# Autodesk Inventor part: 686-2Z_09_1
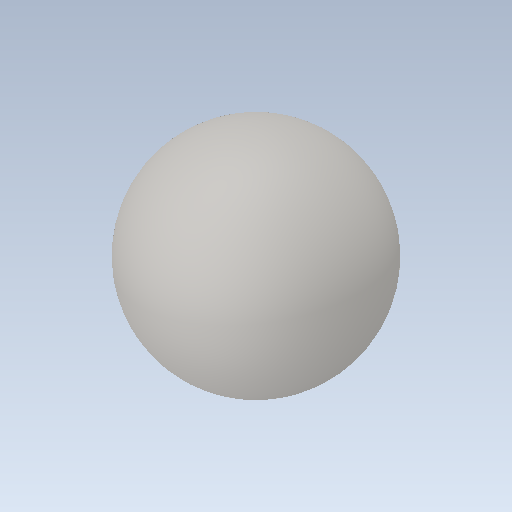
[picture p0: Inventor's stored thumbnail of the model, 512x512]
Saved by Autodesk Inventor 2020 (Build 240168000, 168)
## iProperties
Created: 2017-11
Part Number: 686-2Z_09_1
Material: Ogólny
Document SubType Name: Modeling
Designer: Tomasz
Density: 1 g/cm^3
Appearance: Domyślna
Sending System: SolidWorks 2017
Last Author: Tomasz
Last Saved: 2017-11-19
Source: 686-2Z_09_1
Author: Tomasz
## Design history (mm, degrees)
feature "Imported1"
node "Bryła1"
